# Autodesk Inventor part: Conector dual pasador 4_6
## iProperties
Created: 2008-01
Part Number: Conector dual pasador 4_6
Document SubType Name: Modeling
Designer: eruiz-tagle
Mass: 0.222187 g
Surface Area: 7.57239 cm^2
Volume: 0.222187 cm^3
Density: 1 g/cm^3
Author: eruiz-tagle
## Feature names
1. Extrusion1
2. Revolution1
3. Extrusion2
4. Fillet1
5. Extrusion3
6. Extrusion4
7. Revolution2
8. Extrusion5
9. Extrusion6
10. Fillet2
11. Extrusion7
12. Circular Pattern1
